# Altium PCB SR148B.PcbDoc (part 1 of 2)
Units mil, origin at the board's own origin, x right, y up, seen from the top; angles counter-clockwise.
Board outline 3900 x 2475 mil, 6 copper layers (Top Layer, Signal Layer 1, Signal Layer 2, Signal Layer 3, Signal Layer 4, Bottom Layer), stack 60.536 mil thick; 89 components, 26 nets, 178 pads, 295 vias.
Unrouted connection lines stored in the file: 1.
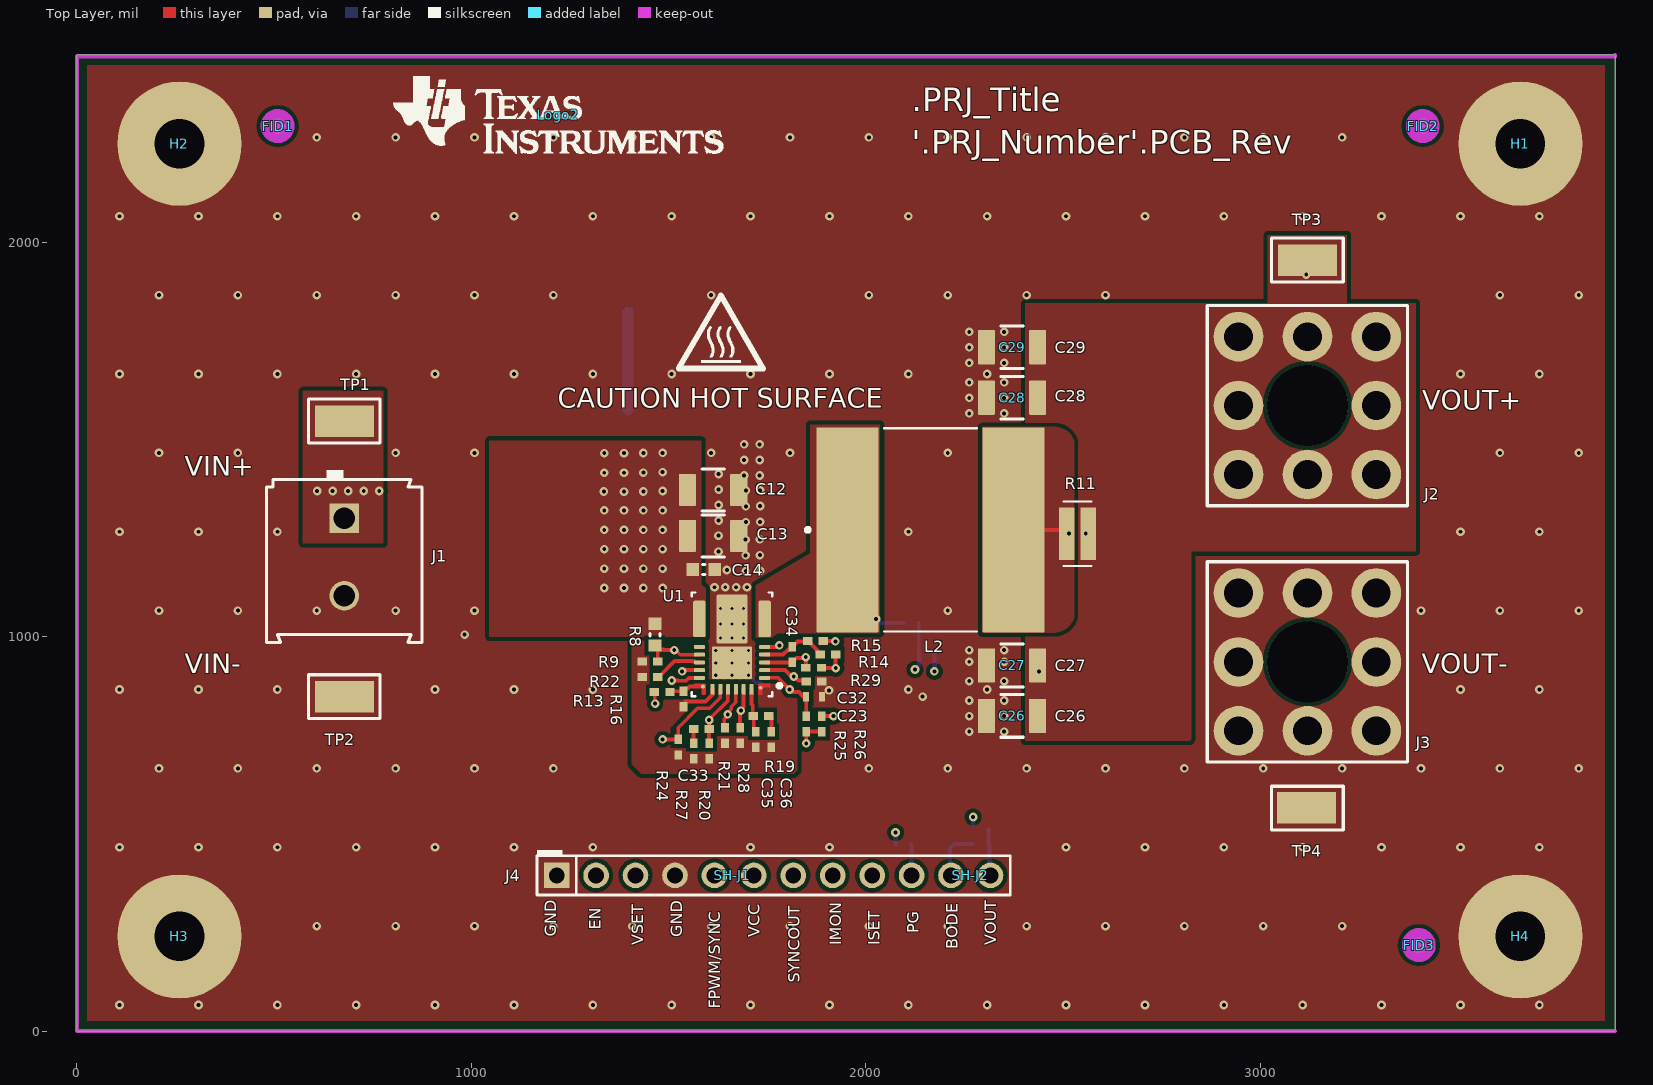
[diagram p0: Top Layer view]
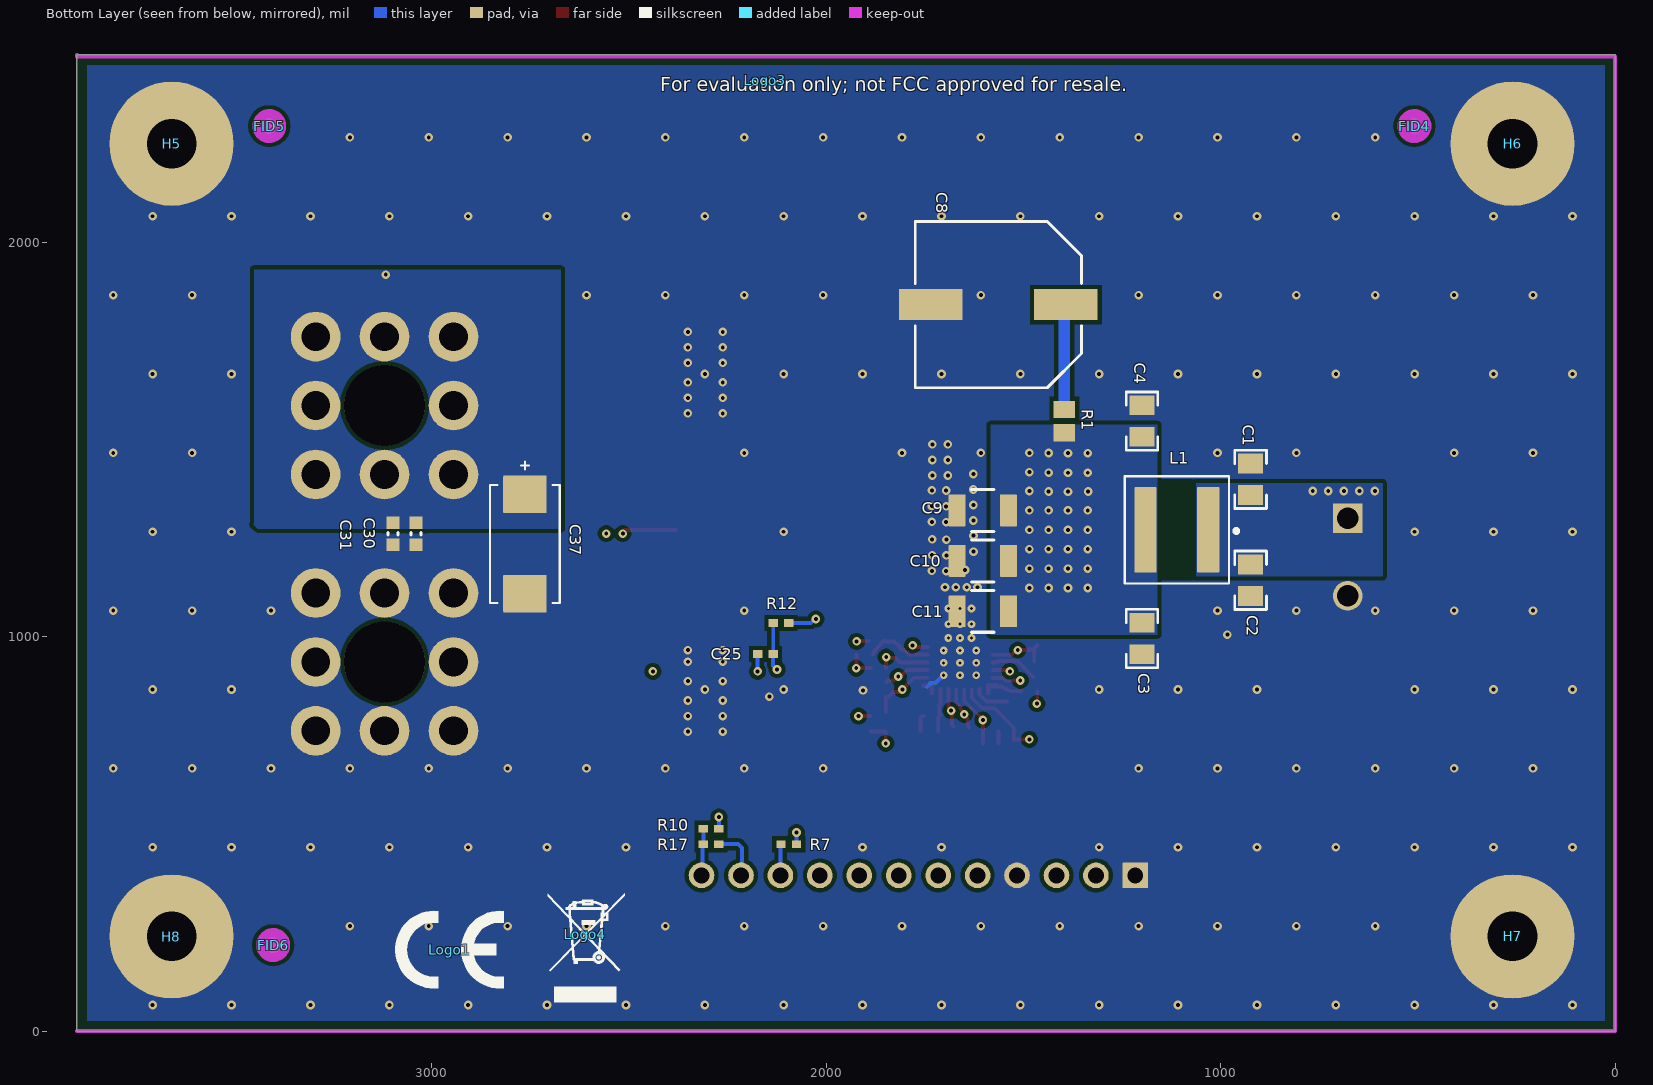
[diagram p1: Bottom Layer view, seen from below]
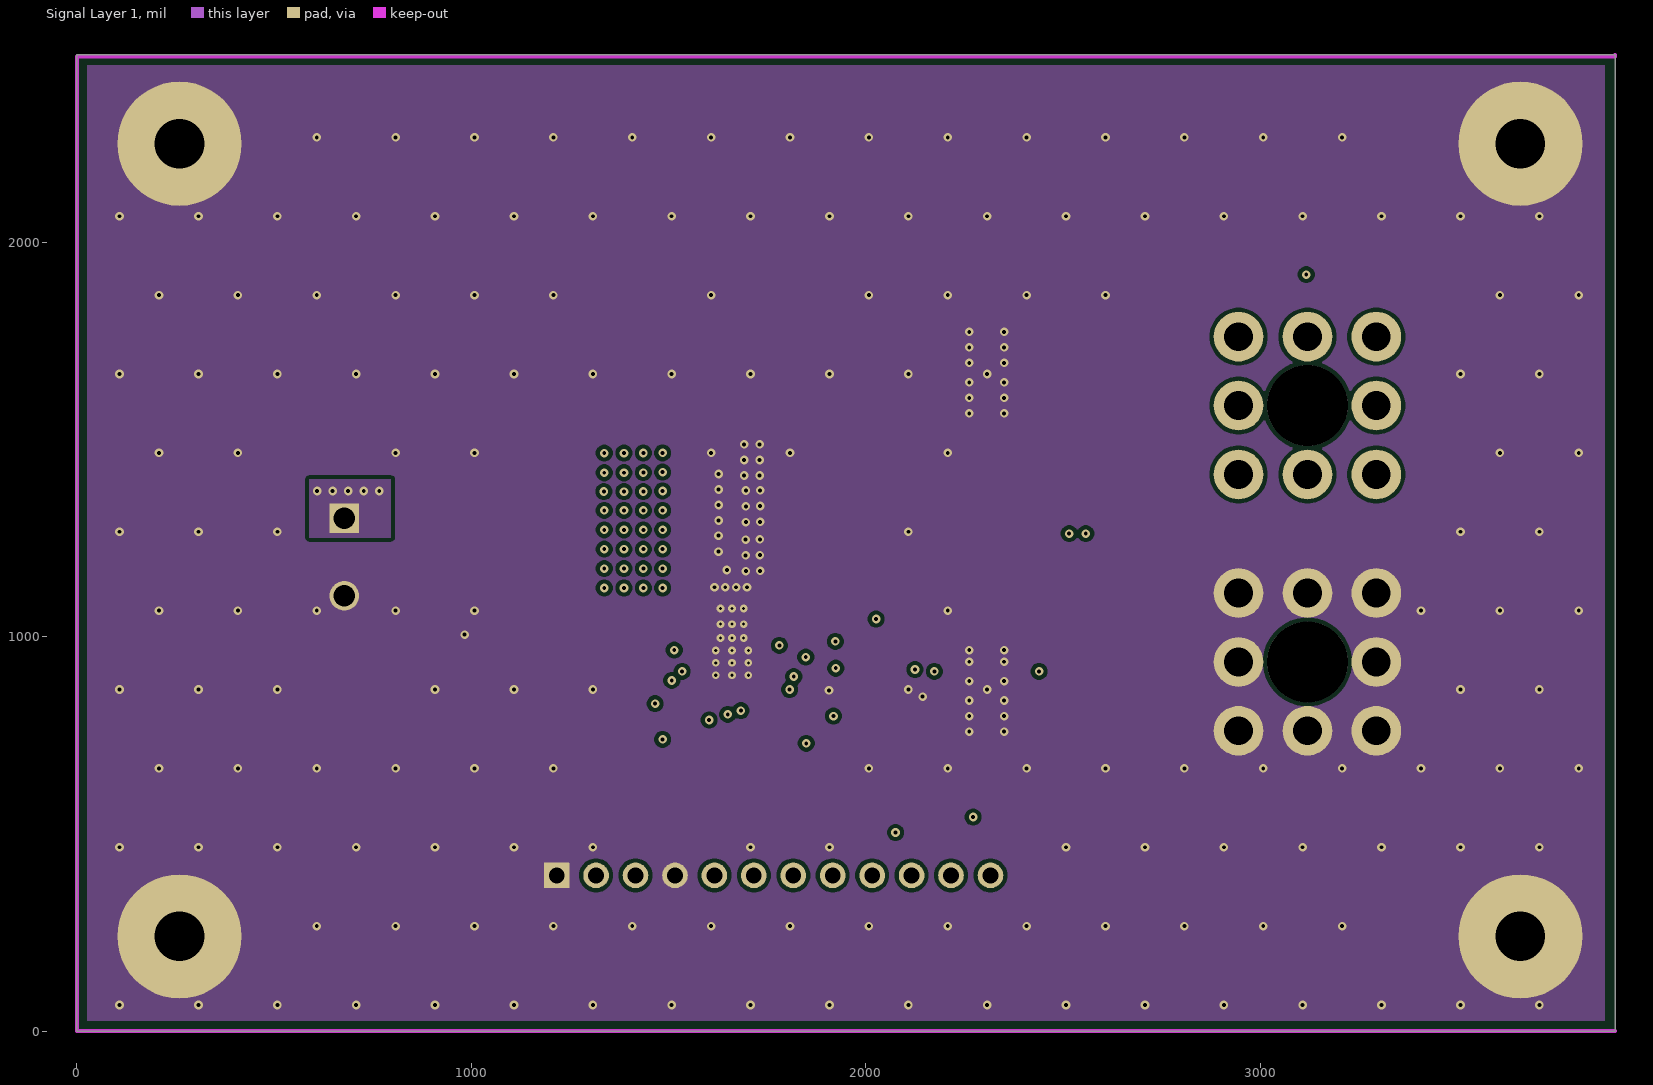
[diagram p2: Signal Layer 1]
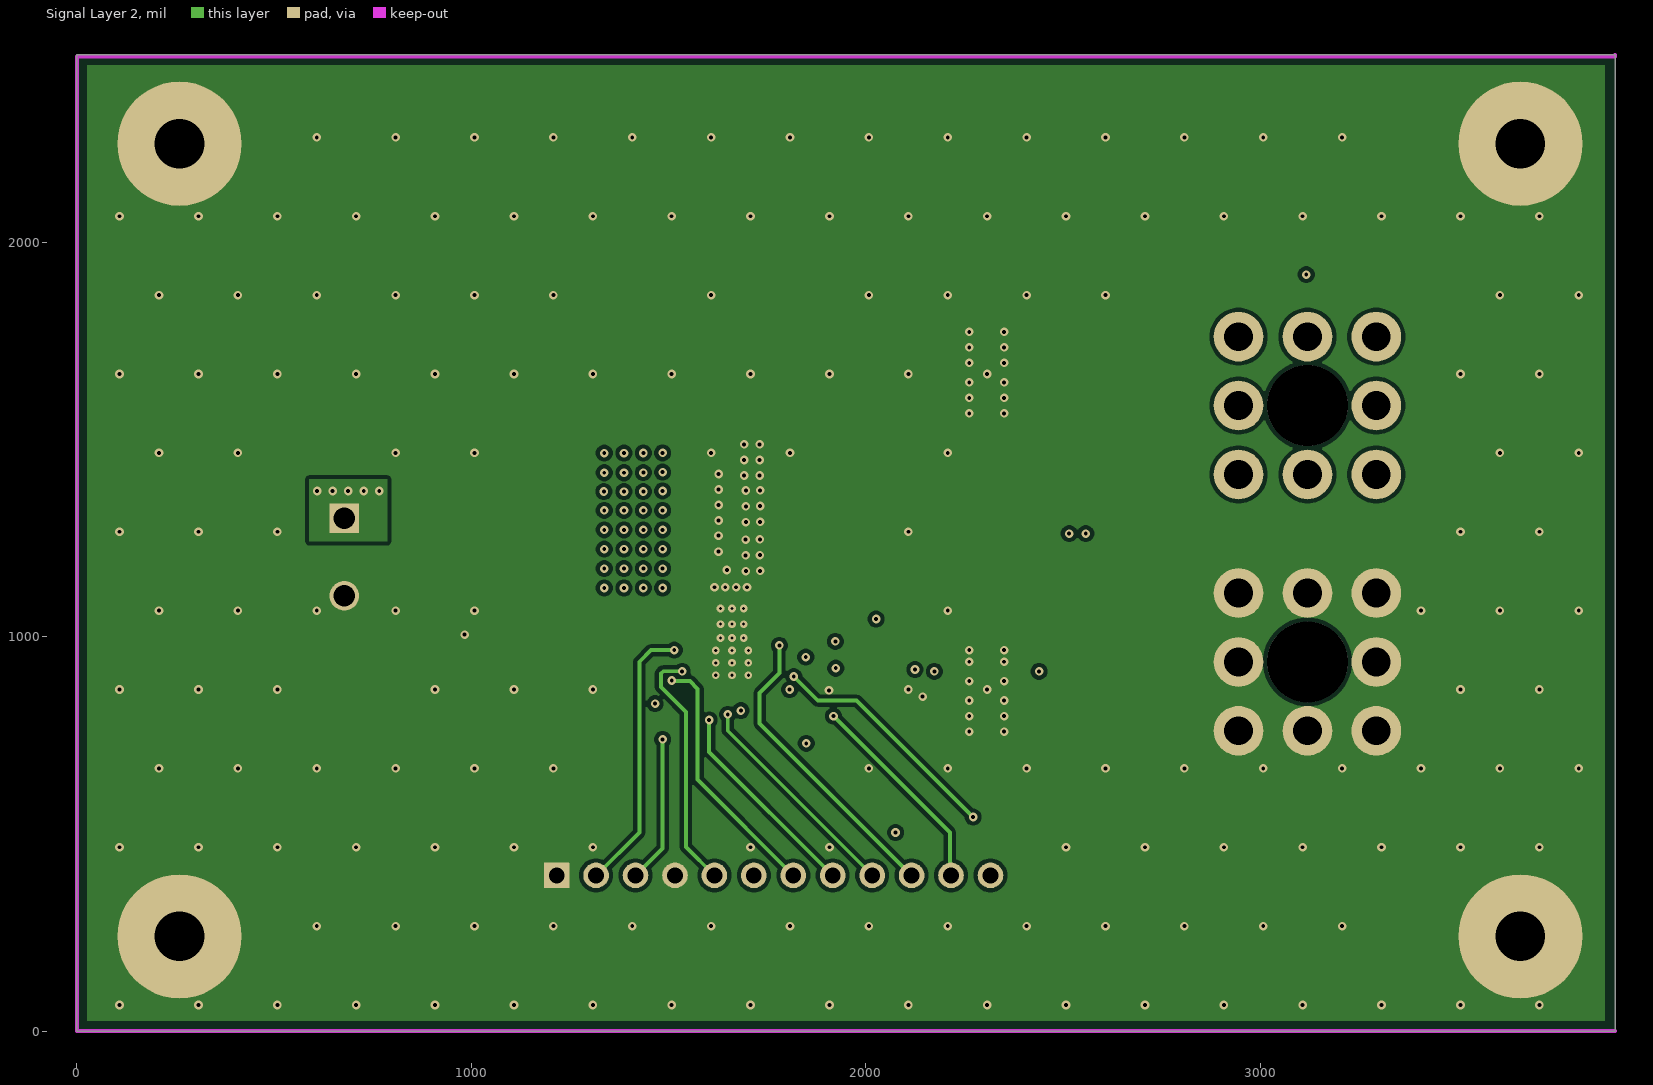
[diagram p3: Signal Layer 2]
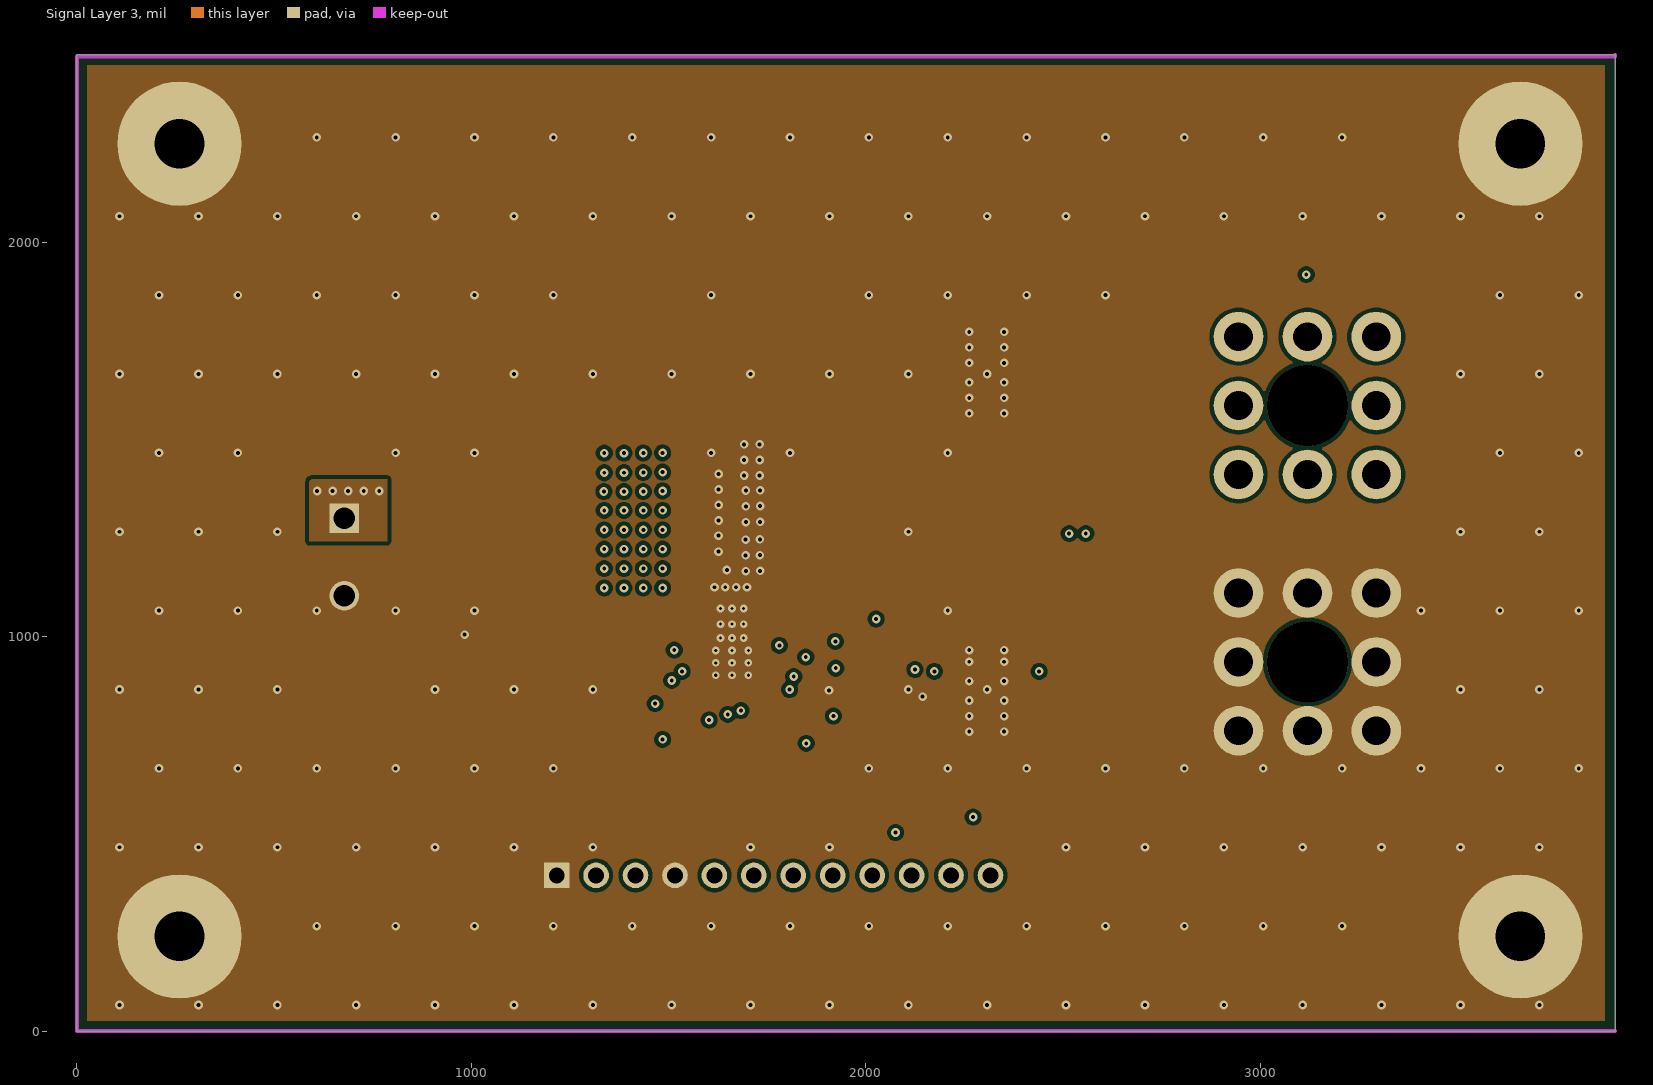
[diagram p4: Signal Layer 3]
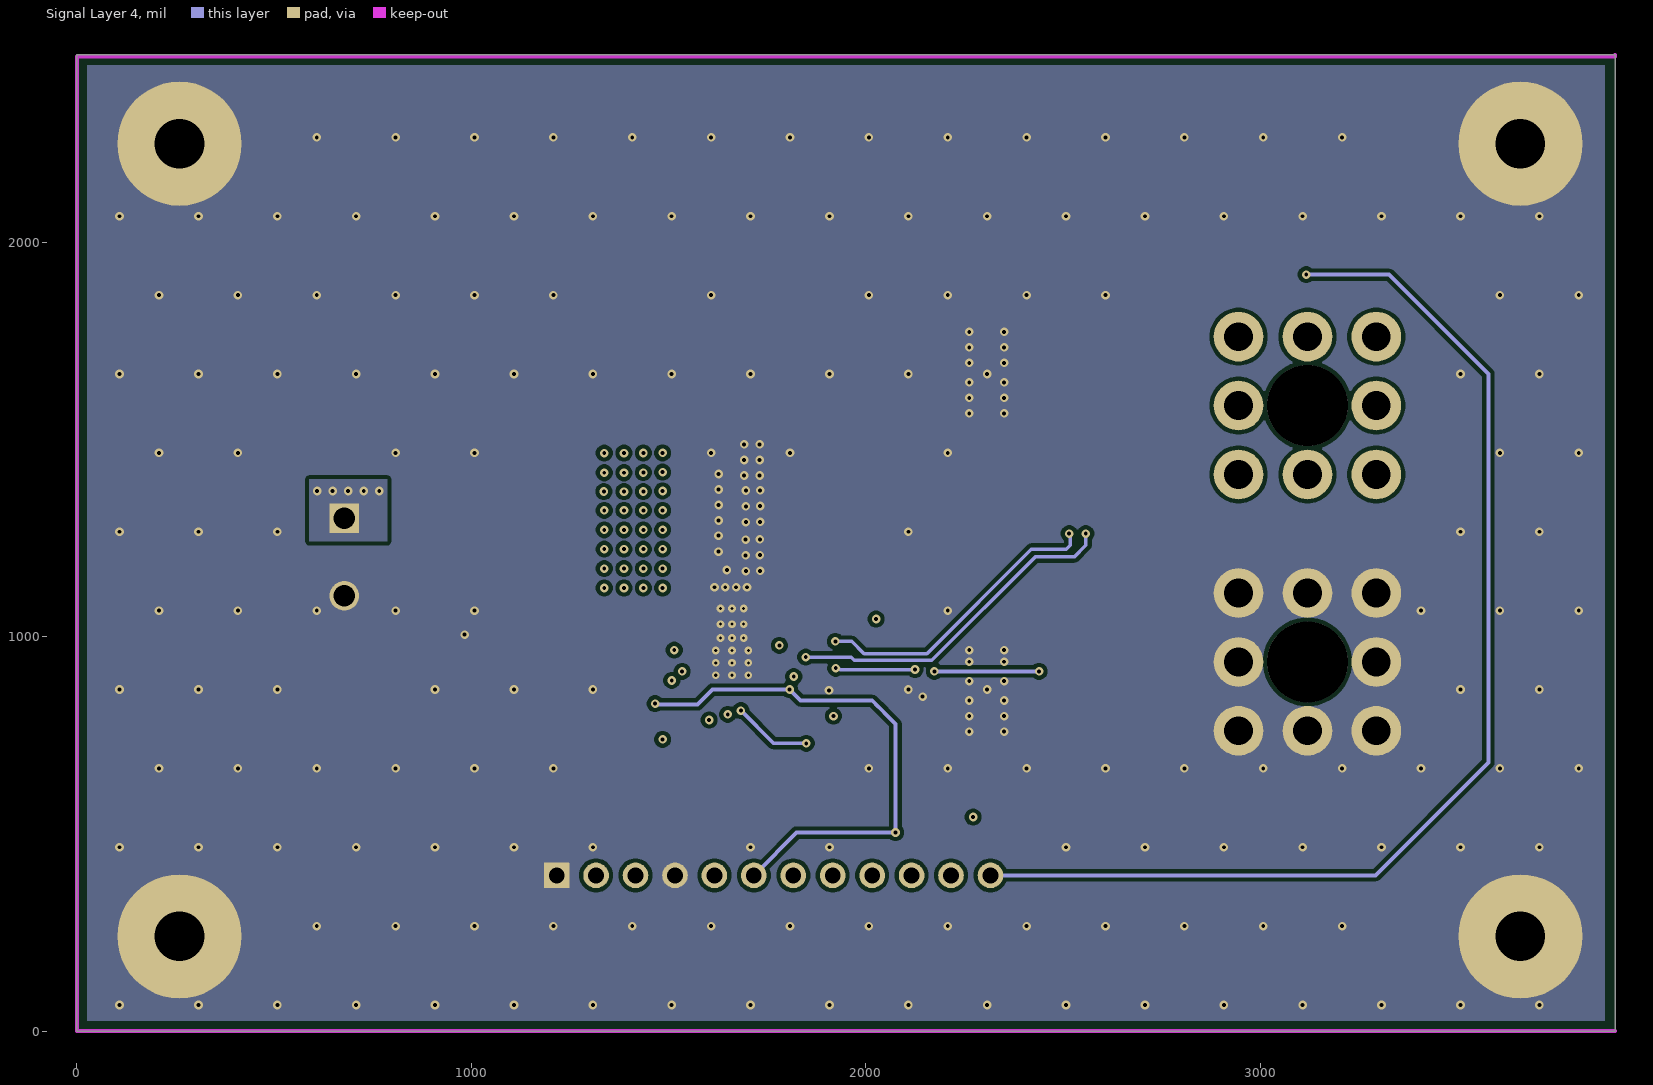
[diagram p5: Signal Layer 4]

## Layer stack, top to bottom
Top Solder: solder mask 0.4, Solder Resist, Dk 3.5
Top Layer: signal copper 2.756
Dielectric 1: prepreg 8, PP-006, Dk 4.1
Signal Layer 1: signal copper 2.756
Dielectric 2: prepreg 8, PP-006, Dk 4.1
Signal Layer 2: signal copper 2.756
Dielectric3: core 12, FR-4 High Tg, Dk 4.8
Signal Layer 3: signal copper 2.756
Dielectric 4: prepreg 8, PP-006, Dk 4.1
Signal Layer 4: signal copper 2.756
Dielectric 5: prepreg 8, PP-006, Dk 4.1
Bottom Layer: signal copper 2.756
Bottom Solder: solder mask 0.4, Solder Resist, Dk 3.5

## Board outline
0,0 3900,0 3900,2475 0,2475

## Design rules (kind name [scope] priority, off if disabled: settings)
AcuteAngle [All] p1: minimum=4.50000000000000E+0001 checktracksonly=FALSE
AssemblyTestPointUsage [All] p1: valid=2
BoardOutlineClearance BoardOutlineClearance_MountingHoles [OnCopper and InComponentClass('Mounting Holes')] p1: gap=39.37 ignorepadtopadclearanceinfootprint=FALSE
BoardOutlineClearance BoardOutlineClearance_Poly [OnCopper and IsPoly] p2: gap=25 ignorepadtopadclearanceinfootprint=FALSE
BoardOutlineClearance [OnCopper and Not InComponentClass('Logo') and not InComponentClass('FiducialMark') and not InRegion(1000,500,4000,800) and not InPoly] p3: gap=40 ignorepadtopadclearanceinfootprint=FALSE
Clearance [InNamedPolygon('TOP_LAYER_GND_P823') vs OnLayer('Top Layer')] p1: gap=10 ignorepadtopadclearanceinfootprint=FALSE
Clearance Clearance_FiducialMark [IsKeepOut and InComponentClass('FiducialMark') vs IsPad and InComponentClass('FiducialMark')] p2: gap=0 ignorepadtopadclearanceinfootprint=TRUE
Clearance Clearance_Keepouts [((IsTrack Or IsArc) And Not InPoly) And IsFree and IsKeepOut vs ((IsTrack Or IsArc) And Not InPoly) And IsFree and IsKeepOut] p3: gap=10 ignorepadtopadclearanceinfootprint=TRUE
Clearance Clearance_Poly [InPolygon] p4: gap=10 ignorepadtopadclearanceinfootprint=TRUE
Clearance Clearance_1 [All] p5: gap=7 ignorepadtopadclearanceinfootprint=TRUE except(0: SMDPad-Fill SMDPad-Poly SMDPad-Region)
ComponentClearance ComponentClearance_MountingHoles_FiducialMarks [InComponentClass('Mounting Holes') vs InComponentClass('FiducialMark')] p1: gap=50 collisioncheckmode=3 verticalgap=10 showdistances=FALSE
ComponentClearance ComponentClearance_Shunt [InComponentClass('Header') vs InComponentClass('Shunt')] p2: gap=0 collisioncheckmode=3 verticalgap=0 showdistances=FALSE
ComponentClearance ComponentClearance_Logo [InComponentClass('Logo')] p3: gap=30 collisioncheckmode=3 verticalgap=10 showdistances=FALSE
ComponentClearance ComponentClearance_ScrewToNut [(HasFootprint('NY PMS 440 0025 PH')) vs (HasFootprint('Keystone_1902C'))] p4: gap=5 collisioncheckmode=3 verticalgap=10 showdistances=FALSE
ComponentClearance ComponentClearance_MountingHoles_Headers [HasFootprint('NY PMS 440 0025 PH') vs HasFootprint('Keystone_1902E')] p5: gap=0 collisioncheckmode=3 verticalgap=0 showdistances=FALSE
ComponentClearance ComponentClearance_MountingHoles [InComponentClass('Mounting Holes') vs InComponentClass('Mounting Holes')] p6: gap=100 collisioncheckmode=3 verticalgap=0 showdistances=FALSE
ComponentClearance ComponentClearance_SmallPassives [HasFootprint('0201*') or HasFootprint('0402*') or HasFootprint('0508') or HasFootprint('0603*') or HasFootprint('0612') or HasFootprint('0805*') or HasFootprint('0815*') or HasFootprint('0830*') or HasFootprint('1206*') or HasFootprint('1210*') or HasFootprint('1808*') or HasFootprint('1812*') or HasFootprint('1825*') or HasFootprint('2010*') or HasFootprint('2220*') or HasFootprint('2225*') or HasFootprint('2512*') or HasFootprint('2728*') or HasFootprint('3518*') vs HasFootprint('0201*') or HasFootprint('0402*') or HasFootprint('0508') or HasFootprint('0603*') or HasFootprint('0612') or HasFootprint('0805*') or HasFootprint('0815*') or HasFootprint('0830*') or HasFootprint('1206*') or HasFootprint('1210*') or HasFootprint('1808*') or HasFootprint('1812*') or HasFootprint('1825*') or HasFootprint('2010*') or HasFootprint('2220*') or HasFootprint('2225*') or HasFootprint('2512*') or HasFootprint('2728*') or HasFootprint('3518*')] p7: gap=10 collisioncheckmode=3 verticalgap=10 showdistances=FALSE
ComponentClearance ComponentClearance_THtoSMT [IsThruComponent vs IsSMTComponent] p8: gap=0 collisioncheckmode=3 verticalgap=0 showdistances=FALSE
ComponentClearance ComponentClearanceConnectors [HasFootprint('FP-CB70-14-190_CONN_TERM_RECT_LUG-MFG') vs HasFootprint('Keystone_6096')] p9: gap=0 collisioncheckmode=3 verticalgap=0 showdistances=FALSE
ComponentClearance ComponentClearance_Inductors [HasFootprint('SER2915L') vs HasFootprint('IHLP-6767GZ')] p10: gap=0 collisioncheckmode=3 verticalgap=0 showdistances=FALSE
ComponentClearance ComponentClearance_indInput [HasFootprint('HC2LP') vs HasFootprint('XAL8080')] p11: gap=0 collisioncheckmode=3 verticalgap=0 showdistances=FALSE
ComponentClearance ComponentClearance_THtoTH [IsThruComponent vs IsThruComponent] p12: gap=20 collisioncheckmode=3 verticalgap=30 showdistances=FALSE
ComponentClearance [All] p13: gap=0 collisioncheckmode=3 verticalgap=0 showdistances=TRUE
DiffPairsRouting [All] p1: maxlimit=100 minlimit=10 mostfreqgap=10 toplayer_minwidth=15 toplayer_maxwidth=15 toplayer_prefwidth=15 midlayer1_minwidth=15 midlayer1_maxwidth=15 midlayer1_prefwidth=15 midlayer2_minwidth=15 midlayer2_maxwidth=15 midlayer2_prefwidth=15 midlayer3_minwidth=15 midlayer3_maxwidth=15 midlayer3_prefwidth=15 midlayer4_minwidth=15 midlayer4_maxwidth=15 midlayer4_prefwidth=15 bottomlayer_minwidth=15 bottomlayer_maxwidth=15 bottomlayer_prefwidth=15 maxuncoupledlength=1000
FabricationTestPointUsage TestPointUsage [All] p1: valid=2 allowmultiple=FALSE
FabricationTestpoint Testpoint [All] p1: side=3 testpointundercomponent=TRUE minsize=40 maxsize=100 preferedsize=60 minholesize=0 maxholesize=40 preferedholesize=32 testpointgrid=1 allowsidetop=TRUE allowsidebottom=TRUE usegrid=TRUE gridtolerance=0.01
FanoutControl Fanout_LCC [IsLCC] p1: bgadir=Out bgaviamode=Centered fanoutstyle=Auto fanoutdirection=Alternating viagrid=1 // Fanout_LCC (Default Rule)
FanoutControl Fanout_BGA [IsBGA] p2: bgadir=Out bgaviamode=Centered fanoutstyle=Auto fanoutdirection=Alternating viagrid=1 // Fanout_BGA (Default Rule)
Height [All] p1: minheight=0 maxheight=1500 prefheight=500
HoleSize [All] p1: absolutevalues=TRUE maxlimit=300 minlimit=7.87 maxpercent=80.000 minpercent=20.000
MinimumAnnularRing MinimumAnnularRing_ThermalPadVias [IsVia and InAnyComponent] p1: minimumring=5.91
MinimumAnnularRing [All] p2: minimumring=0
MinimumSolderMaskSliver MinimumSolderMaskSliver_Logo [InComponentClass('Logo') vs InComponentClass('Logo')] p1: minsoldermaskwidth=0.7
MinimumSolderMaskSliver [All] p2: minsoldermaskwidth=3.94
PlaneClearance [All] p1: clearance=10
PlaneConnect [All] p1: planeconnectstyle=Direct reliefexpansion=10 reliefentries=4 reliefconductorwidth=10 reliefairgap=10
PolygonConnect PolygonConnectStyle_1 [HasFootprint('TSW-112-07-G-S')] p1: connectstyle=Direct reliefconductorwidth=10 reliefentries=4 polygonreliefangle="90 Angle" airgapwidth=10
PolygonConnect [All] p2: connectstyle=Direct reliefconductorwidth=10 reliefentries=4 polygonreliefangle="90 Angle" airgapwidth=10
RoutingVias ThermalPadVias [IsVia and InAnyComponent] p1: holewidth=7.87 width=19.68 viastyle="Through Hole" minholewidth=7.87 minwidth=19.68 maxholewidth=16 maxwidth=32
RoutingVias [All] p2: holewidth=10 width=22 viastyle="Through Hole" minholewidth=7.87 minwidth=20 maxholewidth=40 maxwidth=65
ShortCircuit [InNet('VOUT') vs InNet('VOUT')] p1: allowed=TRUE
SilkToSilkClearance SilkToSilkClearance_Pb-FreeLogo [(HasFootprint('Pb-Free_Overlay_Medium') OR HasFootprint('Pb-Free_Overlay_Small')) vs (HasFootprint('Pb-Free_Overlay_Medium') OR HasFootprint('Pb-Free_Overlay_Small'))] p1: silktosilkclearance=0
SilkToSilkClearance [All] p2: silktosilkclearance=3.94
SilkToSolderMaskClearance SilkToComponentPadClearance [(IsPad or IsFill or IsRegion) and InAnycomponent] p1: minsilkscreentomaskgap=5 clearancetoexposedcopper=TRUE
SilkToSolderMaskClearance "Silk to Solder Mask Opening" [All] p2: minsilkscreentomaskgap=3.94 clearancetoexposedcopper=FALSE
SolderMaskExpansion [All] p1: expansion=1.97 istentingtop=FALSE
SupplyNets "Schematic Supply Nets_4" [InNet('VIN')] p1: voltage=0.000
SupplyNets "Schematic Supply Nets_3" [InNet('VCC')] p2: voltage=0.000
SupplyNets "Schematic Supply Nets_2" [InNet('VOUT')] p3: voltage=0.000
SupplyNets "Schematic Supply Nets_1" [InNet('AGND')] p4: voltage=0.000
SupplyNets "Schematic Supply Nets" [InNet('GND')] p5: voltage=0.000
UnRoutedNet [InNet('PGND')] p1: checkbadconnections=TRUE
Width [All] p1: maxlimit=100 minlimit=6 preferedwidth=10 checkconnectedcopper=TRUE
14 further rules are at their usual default settings.

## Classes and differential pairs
component class FiducialMark: FID1 FID2 FID3 FID4 FID5 FID6
component class "Mounting Holes": H1 H2 H3 H4
component class Logo: Logo2
component class SR148B_Hardware: !PCB1 "CAUTION HOT SURFACE" FID1 FID2 FID3 FID4 FID5 FID6 H1 H2 H3 H4 H5 H6 H7 H8 Logo1 Logo2 Logo3 Logo4 SH-J1 SH-J2 ZZ1 ZZ2 ZZ3 ZZ4 ZZ5 ZZ6
component class AssemblyNote: ZZ1 ZZ2 ZZ3 ZZ4 ZZ5 ZZ6
component class SR148B: C1 C2 C3 C4 C8 C9 C10 C11 C12 C13 C14 C23 C25 C26 C27 C28 C29 C30 C31 C32 C33 C34 C35 C36 C37 J1 J2 J3 J4 L1 L2 R1 R7 R8 R9 R10 R11 R12 R13 R14 R15 R16 R17 R19 R20 R21 R22 R24 R25 R26 R27 R28 R29 TP1 TP2 TP3 TP4 U1 U2_S1
component class Header: J4

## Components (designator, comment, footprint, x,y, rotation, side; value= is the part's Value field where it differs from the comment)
C1 "GRM21BR72A474KA73L" 0805_HV 924,1398.95 r90 bottom value=0.47uF
C2 "GRM21BR72A474KA73L" 0805_HV 924,1143.05 r270 bottom value=0.47uF
C3 "GRM21BR72A474KA73L" 0805_HV 1199.59,995.41 r270 bottom value=0.47uF
C4 "GRM21BR72A474KA73L" 0805_HV 1199.59,1546.59 r90 bottom value=0.47uF
C8 "EEE-FK2A330P" SM_RADIAL_G 1563.76,1841.87 r0 bottom value=33uF
C9 "GRM32EC72A106KE05L" FP-GRM32EC72A106KE05L_1210-MFG 1603.13,1320.21 r0 bottom
C10 "GRM32EC72A106KE05L" FP-GRM32EC72A106KE05L_1210-MFG 1603.13,1192.26 r0 bottom
C11 "GRM32EC72A106KE05L" FP-GRM32EC72A106KE05L_1210-MFG 1603.13,1064.31 r0 bottom
C12 "GRM32EC72A106KE05L" FP-GRM32EC72A106KE05L_1210-MFG 1613,1372 r0 top
C13 "GRM32EC72A106KE05L" FP-GRM32EC72A106KE05L_1210-MFG 1613,1255.53 r0 top
C14 "CGA3E2X8R2A103K080AD" 0603L 1589.29,1169.94 r0 top value=0.01uF
C23 "GRT155C71A225KE13" 0402_070 1868.88,847.77 r0 top value=2.2uF
C25 "CGA2B3X7R1E104K050BB" 0402L 2154,956.04 r0 bottom value=0.1uF
C26 "GCM32EC71A476KE02K" FP-GCM32EC71A476KE02K_1210-MFG 2371,799 r0 top
C26 "CGA6P3X7R1E226M250AB" FP-CGA6P3X7R1E226M250AB_1210-MFG 2371,799 r0 top value=22µF
C27 "GCM32EC71A476KE02K" FP-GCM32EC71A476KE02K_1210-MFG 2371,927 r0 top
C27 "CGA6P3X7R1E226M250AB" FP-CGA6P3X7R1E226M250AB_1210-MFG 2371,927 r0 top value=22µF
C28 "CGA6P3X7R1E226M250AB" FP-CGA6P3X7R1E226M250AB_1210-MFG 2371,1606 r0 top value=22µF
C28 "GCM32EC71A476KE02K" FP-GCM32EC71A476KE02K_1210-MFG 2371,1606 r0 top
C29 "CGA6P3X7R1E226M250AB" FP-CGA6P3X7R1E226M250AB_1210-MFG 2371,1734 r0 top value=22µF
C29 "GCM32EC71A476KE02K" FP-GCM32EC71A476KE02K_1210-MFG 2371,1734 r0 top
C30 "C0603C104K5RACTU" 0603L 3040,1261 r270 bottom value=0.1uF
C31 "C0603C104K5RACTU" 0603L 3099,1261 r270 bottom value=0.1uF
C32 "CGA2B3X7R1E104K050BB" 0402L 1869,886 r0 top value=0.1uF
C33 "CGA2B3X8R1H103K050BB" 0402L 1583.45,766 r0 top value=0.01uF
C34 "CGA2B2C0G1H101J050BA" 0402L 1814,955 r270 top value=100pF
C35 "CGA2B2C0G1H470J050BA" 0402L 1721,739.5 r270 top value=47pF
C36 "GRM155R71H272KA01D" 0402L 1760.61,739.5 r270 top value=2700pF
C37 "ECASD61C107M012KA0" FP-ECASD61C107M012KA0_2917-MFG 2764,1235 r90 bottom value=100µF
"CAUTION HOT SURFACE" "CAUTION HOT SURFACE" IEC_HotSurface_Small 1632.66,1772.97 r0 top
FID1 "Fiducial" Fiducial10-20 508.78,2294.74 r90 top
FID2 "Fiducial" Fiducial10-20 3412.32,2294.74 r90 top
FID3 "Fiducial" Fiducial10-20 3402.48,217.97 r90 top
FID4 "Fiducial" Fiducial10-20 508.78,2294.74 r90 bottom
FID5 "Fiducial" Fiducial10-20 3412.32,2294.74 r90 bottom
FID6 "Fiducial" Fiducial10-20 3402.48,217.97 r90 bottom
H1 "NY PMS 440 0025 PH" "NY PMS 440 0025 PH" 3660,2250 r0 top
H2 "NY PMS 440 0025 PH" "NY PMS 440 0025 PH" 260,2250 r0 top
H3 "NY PMS 440 0025 PH" "NY PMS 440 0025 PH" 260,240 r0 top
H4 "NY PMS 440 0025 PH" "NY PMS 440 0025 PH" 3660,240 r0 top
H5 "1902C" Keystone_1902E 3660,2250 r180 bottom
H6 "1902C" Keystone_1902E 260,2250 r180 bottom
H7 "1902C" Keystone_1902E 260,240 r180 bottom
H8 "1902C" Keystone_1902E 3660.63,239.37 r180 bottom
J1 "282856-2" TE_282856-2 677.94,1202.1 r270 top
J2 "74655095R" FP-74655095R_CONN_TERM_10MM0_10MM0-MFG 3120,1586 r0 top
J3 "74655095R" FP-74655095R_CONN_TERM_10MM0_10MM0-MFG 3120,936 r0 top
J4 "TSW-112-07-G-S" TSW-112-07-G-S 1766.3,394.69 r0 top
L1 "XGL6060-332MEC" FP-XGL6060-332MEC_SMT_6MM51_6MM71-MFG 1111.01,1271 r0 bottom value=3.3uH
L2 "VCUD128T-4R7MS8" FP-VCUD128T-4R7MS8_SMT_IND_13MM3_12MM8-MFG 2164.16,1271 r0 top value=4.7uH
Logo1 "CE Mark" CE_Mark_5mm 2954.99,206.33 r180 bottom
Logo2 "Texas Instruments" TI_Stacked_Overlay_Small 1220.47,2322.83 r0 top
Logo3 "FCC disclaimer" FCC_disclaimer 2155,2411 r180 bottom
Logo4 "WEEE logo" WEEE_Minimum 2610.87,244.86 r180 bottom
R1 "ERJ-6GEY0R00V" 0805L 1396.44,1546.59 r270 bottom value=0
R7 "AC0402FR-07100KL" 0402L 2095.26,473.76 r180 bottom value=100k
R8 "RC0603FR-07200KL" 0603L 1465.34,1005.25 r90 top value=200k
R9 "ERJPA2F1002X" 0402L 1453,937.2 r0 top value=10.0k
R10 "CRCW04021R00FKED" 0402L 2292.11,513.13 r0 bottom value=1.00
R11 "KRL3216E-C-R001-J-T5" FP-KRL3216E-C-R001-J-T5_0612-MFG 2537,1261 r0 top value=1m
R12 "ERJPA2F1002X" 0402L 2114.94,1034.78 r0 bottom value=10.0k
R13 "CRCW040254K9FKED" 0402L 1483.82,860 r180 top value=54.9k
R14 "RK73Z1ETTP" 0402L 1904,955 r0 top value=0
R15 "ERJ-2RKF49R9X" 0402L 1873,989 r0 top value=49.9
R16 "CRCW040254K9FKED" 0402L 1538.27,842.1 r90 top value=54.9k
R17 "ERJ-2RKF49R9X" 0402L 2292.11,473.76 r0 bottom value=49.9
R19 "CRCW040211K0FKED" 0402L 1734.29,798.59 r180 top value=11.0k
R20 "CRCW04028K66FKED" 0402L 1603.13,709.98 r90 top value=8.66k
R21 "CRCW040290K9FKED" 0402L 1643,749.35 r90 top value=90.9k
R22 "CRCW040223K7FKED" 0402L 1453,897.63 r0 top value=23.7k
R24 "CRCW040290K9FKED" 0402L 1524.39,719.82 r90 top value=90.9k
R25 "RK73Z1ETTP" 0402L 1849.2,778.87 r90 top value=0
R26 "CRCW040254K9FKED" 0402L 1888.57,778.87 r90 top value=54.9k
R27 "RK73Z1ETTP" 0402L 1563.76,709.98 r90 top value=0
R28 "ERA-2AEB4991X" 0402L 1681.87,749.35 r90 top value=4.99k
R29 "AC0402FR-07100KL" 0402L 1868,921 r0 top value=100k
SH-J1 "M7582-05" Harwin_M7582-05 1662,395 r180 top
SH-J2 "M7582-05" Harwin_M7582-05 2265,395 r180 top
TP1 "5019" Keystone_5019#1 677.94,1546.59 r0 top
TP2 "5019" Keystone_5019#1 677.94,847.77 r0 top
TP3 "5019" Keystone_5019#1 3120,1955 r0 top
TP4 "5019" Keystone_5019#2 3120,565 r0 top
U1 "LMG708B0VBTR" VBT0022B-MFG 1661,979 r180 top
ZZ1 "This Assembly Note is for PCB labels only" AssemblyNoteLabel 19.68,3357.28 r0 top
ZZ2 "These assemblies are ESD sensitive, ESD precautions shall be observed." AssemblyNote 19.68,3257.28 r0 top
ZZ3 "These assemblies must be clean and free from flux and all contaminants. Use of no clean flux is not acceptable." AssemblyNote 19.68,3157.28 r0 top
ZZ4 "These assemblies must comply with workmanship standards IPC-A-610 Class 2, unless otherwise specified." AssemblyNote 19.68,3061.02 r0 top
ZZ5 "Install Shunt Jumper SH-J1 onto J4 Pins 5-6" AssemblyNote 19.68,2952.76 r0 top
ZZ6 "Install Shunt Jumper SH-J2 onto J4 Pins 11-12" AssemblyNote 22,2844 r0 top

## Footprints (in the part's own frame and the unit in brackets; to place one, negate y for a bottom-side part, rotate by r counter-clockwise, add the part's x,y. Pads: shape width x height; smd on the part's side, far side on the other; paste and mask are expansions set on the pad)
0402_070 [mil] "SMD, 2-Leads, Body 1.2x0.7mm, Height 0.7mm"
  rect 15x24 smd: 1(-20,0) 2(20,0)
  body extent -24,-14 24,14, height 28
0402L [mm] "0402 from SM-752 data"
  rect 0.6x0.5 smd: 1(-0.5,0) 2(0.5,0)
  body extent -0.55,-0.3 0.55,0.3, height 0.6
0603L [mm] "0603 from SM-752 data"
  rect 0.8x0.85 smd: 1(-0.7,0) 2(0.7,0)
  silkscreen extent -0.07,-0.33 0.07,0.33, body extent -0.87,-0.47 0.87,0.47, height 1
0805_HV [mil] "0805 with 30mil clearance between pads"
  rect 50x63 smd: 1(-40,0) 2(40,0)
  silkscreen extent -74,-40 74,40, body extent -43,-29 43,29, height 57
0805L [mm] "0805 from SM-752 data"
  rect 1.1x1.4 smd: 1(-0.75,0) 2(0.75,0)
  body extent -1.1,-0.72 1.1,0.72, height 1.45
AssemblyNote [mil] "Assembly Note"
AssemblyNoteLabel [mil] "Assembly Note for PCB Labels"
CE_Mark_5mm [mil] "Minimum text height for CE Mark"
  silkscreen extent -138,-98 138,98
FCC_disclaimer [mil]
Fiducial10-20 [mm]
  round 1 smd mask+0.5: 1(0,0)
  Top Layer keep-out circle w1.178: c0,0 r0.5
FP-74655095R_CONN_TERM_10MM0_10MM0-MFG [mm]
  round 3.2 hole 1.85 paste-2539.97 mask+0: 1(-4.435,-4.435) 1(-4.435,0) 1(-4.435,4.435) 1(0,-4.435) 1(0,4.435) 1(4.435,-4.435) 1(4.435,0) 1(4.435,4.435)
  round 5.2 hole 5.2 unplated paste-2539.97 mask+0: ""(0,0)
  silkscreen extent -6.45,-6.45 6.45,6.45, body extent -6.13,-6.13 6.13,6.13, height 0.25
FP-CGA6P3X7R1E226M250AB_1210-MFG [mm]
  rrect9% 1.1x2.2 smd paste+0 mask+0: 1(-1.65,0) 2(1.65,0)
  silkscreen extent -0.72,-1.4 0.72,1.4, body extent -2.3,-1.5 2.3,1.5, height 0.25
FP-ECASD61C107M012KA0_2917-MFG [mm] "Recommended Land Pattern"
  rrect4% 2.4x2.8 smd paste+0 mask+0: 1(-3.2,0) 2(3.2,0)
  silkscreen extent -3.8,-2.25 5.3,2.25, body extent -3.65,-2.15 3.65,2.15, height 3.1
FP-GCM32EC71A476KE02K_1210-MFG [mm]
  rrect9% 1.1x2.05 smd paste+0 mask+0: 1(-1.65,0) 2(1.65,0)
  silkscreen extent -0.72,-1.35 0.72,1.35, body extent -2.3,-1.45 2.3,1.45, height 0.25
FP-GRM32EC72A106KE05L_1210-MFG [mm]
  rrect9% 1.1x2.05 smd paste+0 mask+0: 1(-1.65,0) 2(1.65,0)
  silkscreen extent -0.72,-1.35 0.72,1.35, body extent -1.6,-1.25 1.6,1.25, height 2.7
FP-KRL3216E-C-R001-J-T5_0612-MFG [mm] "Recommended Land Pattern"
  rrect10% 1x3.4 smd paste+0 mask+0: 1(-0.7,0) 2(0.7,0)
  silkscreen extent -0.9,-2.07 0.9,2.07, body extent -1.3,-1.8 1.3,1.8, height 0.25
FP-VCUD128T-4R7MS8_SMT_IND_13MM3_12MM8-MFG [mm] "Recommended Land Pattern"
  rrect3% 4x13.2 smd paste+0 mask+0: 1(-5.35,0) 2(5.35,0)
  silkscreen extent -8.02,-6.55 2.98,6.55, body extent -7.45,-6.7 7.45,6.7, height 0.25
FP-XGL6060-332MEC_SMT_6MM51_6MM71-MFG [mm]
  rrect7% 1.43x5.5 smd paste+0 mask+0: 1(-2.02,0) 2(2.02,0)
  silkscreen extent -3.95,-3.45 3.35,3.45, body extent -3.25,-3.35 3.25,3.35, height 6.1
Harwin_M7582-05 [mil] "Single Operation 2.54mm Pitch Open Top Jumper Socket"
  body extent -98,-47 98,47, height 236
IEC_HotSurface_Small [mil]
  silkscreen extent -107,-93 107,92
Keystone_1902E [mil] "Hex Standoff, 4-40 threaded, nylon"
  round 1 on Mech4: 0(0,0)
  body extent -145,-126 146,126, height 1001
Keystone_5019#1 [mm] "Test Point, Miniature, SMT"
  rect 3.8x2.03 smd: 1(0,0)
  silkscreen extent -2.31,-1.42 2.31,1.42, body extent -1.9,-1.02 1.9,1.02, height 2.29
Keystone_5019#2 [mm] "Test Point, Miniature, SMT"
  rect 3.8x2.03 smd: 1(-0.05,0.015)
  silkscreen extent -2.31,-1.42 2.31,1.42, body extent -1.9,-1.02 1.9,1.02, height 2.29
"NY PMS 440 0025 PH" [mm] "4-40 nylon screw and mounting hole"
  round 8 hole 3.2: 1(0,0)
  body extent -3.3,-3.3 3.3,3.3, height 2.69
SM_RADIAL_G [mm] "10 x 10.2mm:  Panasonic G"
  rect 4.1x2 smd: 1(-4.35,0) 2(4.35,0)
  silkscreen extent -5.35,-5.35 5.35,5.35, body extent -5.25,-5.25 5.25,5.25, height 10.5
TE_282856-2 [mm] "TH, 2-Leads, Body 10x10mm, Pitch 5mm"
  rect 1.9x1.9 hole 1.4: 1(-2.5,0)
  round 1.9 hole 1.4: 2(2.5,0)
  silkscreen extent -5.61,-5 5.5,5, body extent -5,-5 5.5,5, height 19
TI_Stacked_Overlay_Small [mil]
  silkscreen extent -418,-98 418,98
TSW-112-07-G-S [mm] "Samtec 100mil, 1x12, 230 mil above insulator"
  rrect6% 1.65x1.65 hole 1.016 mask+0: 1(-13.97,0)
  round 1.65 hole 1.016 mask+0: 2(-11.43,0) 3(-8.89,0) 4(-6.35,0) 5(-3.81,0) 6(-1.27,0) 7(1.27,0) 8(3.81,0) 9(6.35,0) 10(8.89,0) 11(11.43,0) 12(13.97,0)
  silkscreen extent -15.24,-1.27 15.24,1.65, body extent -15.24,-1.27 15.24,1.27, height 8.38
VBT0022B-MFG [mm] "Recommended Land Pattern"
  round 0.234 smd paste+0 mask+0: 1(-1.837,2.762)
  rrect40% 0.7x0.25 smd paste+0 mask+0: 2(-2.1,2.125) 3(-2.1,1.625) 4(-2.1,1.125) 5(-2.1,0.625) 6(-2.1,0.125) 10(2.1,0.125) 11(2.1,0.625) 12(2.1,1.125) 13(2.1,1.625) 14(2.1,2.125)
  rrect25% 0.8x2.35 smd paste-1000 mask-1000: 7(-2.1,-1.675) 9(2.1,-1.675)
  rrect10% 2x3.15 smd paste-1000 mask-1000: 8(0,-1.675)
  round 0.265 smd paste+0 mask+0: 15(1.875,2.675)
  rrect40% 0.25x0.7 smd paste+0 mask+0: 16(1.25,2.85) 17(0.75,2.85) 18(0.25,2.85) 19(-0.25,2.85) 20(-0.75,2.85) 21(-1.25,2.85)
  rrect10% 2.6x2.1 smd paste-1000 mask-1000: 22(0,1.15)
  Top Layer region: -2.4,2.5 -2.419,2.504 -2.435,2.515 -2.446,2.531 -2.45,2.55 -2.45,2.55 -2.45,2.7 -2.443,2.725 -2.425,2.743 -2.4,2.75 -2.4,2.75 -2.05,2.75 -2.012,2.758 -1.979,2.779 -1.958,2.812 -1.95,2.85 -1.95,2.85 -1.95,3.15 -1.943,3.175 -1.925,3.193 -1.9,3.2 -1.9,3.2 -1.75,3.2 -1.725,3.193 -1.707,3.175 -1.7,3.15 -1.7,3.15 -1.7,2.55 -1.704,2.531 -1.715,2.515 -1.731,2.504 -1.75,2.5 -1.75,2.5
  Top Layer region: 2.4,2.5 2.419,2.504 2.435,2.515 2.446,2.531 2.45,2.55 2.45,2.55 2.45,2.7 2.446,2.719 2.435,2.735 2.419,2.746 2.4,2.75 2.4,2.75 2.05,2.75 2.012,2.758 1.979,2.779 1.958,2.812 1.95,2.85 1.95,2.85 1.95,3.15 1.946,3.169 1.935,3.185 1.919,3.196 1.9,3.2 1.9,3.2 1.75,3.2 1.725,3.193 1.707,3.175 1.7,3.15 1.7,3.15 1.7,2.55 1.704,2.531 1.715,2.515 1.731,2.504 1.75,2.5 1.75,2.5
  silkscreen extent -3.18,-3.37 2.6,3.3, body extent -2.25,-3 2.25,3, height 0.85
WEEE_Minimum [mil] "WEEElie bin"
  silkscreen extent -95,-172 99,104

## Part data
C1 C2 C3 C4: library part CMP-0008374-2, "CAP, CERM, 0.47 uF, 100 V, +/- 10%, X7R, 0805", Cap_Case=0805, Manufacturer=MuRata, Supplier Part Number 1=490-3326-1-ND, TempCo=X7R, Tolerance_%=10%, Value1=Unknown, Value2=100V, ValueDisplayed=0.47uF
C8: library part CMP-0011203-2, "CAP, AL, 33 uF, 100 V, +/- 20%, 0.7 ohm, AEC-Q200 Grade 2, SMD", Cap_Case=G, Manufacturer=Panasonic, Supplier Part Number 1=PCE3846CT-ND, Tolerance_%=20%, Value1="0.7 ohm", Value2=100V, ValueDisplayed=33uF
C9 C10 C11 C12 C13: library part CMP-0087970-1, "10µF ±10% 100V Ceramic Capacitor X7S 1210 (3225 Metric)", Manufacturer=Murata, TempCo=22%, Tolerance_%=10%, ValueDisplayed=10uF
C14: library part CMP-0080063-1, "CAP, CERM, 0.01 µF, 100 V,+/- 10%, X8R, AEC-Q200 Grade 0, 0603", Cap_Case=0603, Manufacturer=TDK, Supplier Part Number 1=445-8825-1-ND, TempCo=X8R, Tolerance_%=10%, Value2=100V, ValueDisplayed=0.01µF
C23: library part CMP-0086250-1, "CAP, CERM, 2.2 µF, 10 V,+/- 10%, X7S, AEC-Q200 Grade 1, 0402", Cap_Case=0402, Manufacturer=MuRata, TempCo=X7S, Tolerance_%=10%, Value2=10V, ValueDisplayed=2.2µF
C25 C32: library part CMP-0080610-1, "CAP, CERM, 0.1 µF, 25 V,+/- 10%, X7R, AEC-Q200 Grade 1, 0402", Cap_Case=0402, Manufacturer=TDK, Supplier Part Number 1=445-6902-1-ND, TempCo=X7R, Tolerance_%=10%, Value2=25V, ValueDisplayed=0.1µF
C26 C27 C28 C29: library part CMP-0096011-1, "Ceramic Capacitor for Automotive 47uF ±10% 10VDC X7S 1210 Embossed T/R"
C26 C27 C28 C29: library part CMP-0036912-1, "Cap Ceramic 22uF 25V X7R 20% Pad SMD 1210 +125°C Automotive T/R", Manufacturer=TDK, Operating Temperature Range="-55°C to +125°C", TempCo=15%, Temperature Characteristic=X7R, Tolerance_%=0.2%, ValueDisplayed=22uF
C30 C31: library part CMP-0006861-4, "CAP, CERM, 0.1 uF, 50 V, +/- 10%, X7R, 0603", Cap_Case=0603, Manufacturer=Kemet, Supplier Part Number 1=399-5089-1-ND, TempCo=X7R, Tolerance_%=10%, Value1=Unknown, Value2=50V, ValueDisplayed=0.1uF
C33: library part CMP-0078224-1, "CAP, CERM, 0.01 µF, 50 V,+/- 10%, X8R, AEC-Q200 Grade 0, 0402", Cap_Case=0402, Manufacturer=TDK, Supplier Part Number 1=445-12303-1-ND, TempCo=X8R, Tolerance_%=10%, Value2=50V, ValueDisplayed=0.01µF
C34: library part CMP-0006308-2, "CAP, CERM, 100 pF, 50 V, +/- 5%, C0G/NP0, AEC-Q200 Grade 1, 0402", Cap_Case=0402, Manufacturer=TDK, Supplier Part Number 1=445-5596-1-ND, TempCo=C0G/NP0, Tolerance_%=5%, Value1=Unknown, Value2=50V, ValueDisplayed=100pF
C35: library part CMP-0860832-1, "CAP, CERM, 47 pF, 50 V,+/- 5%, C0G/NP0, AEC-Q200 Grade 1, 0402", Cap_Case=0402, Manufacturer=TDK, TempCo=C0G/NP0, Tolerance_%=5%, Value2=50V, ValueDisplayed=47pF
C36: library part CMP-0006686-2, "CAP, CERM, 2700 pF, 50 V, +/- 10%, X7R, 0402", Cap_Case=0402, Manufacturer=MuRata, Supplier Part Number 1=490-1306-1-ND, TempCo=X7R, Tolerance_%=10%, Value1=Unknown, Value2=50V, ValueDisplayed=2700pF
C37: library part CMP-0124193-1, "100 µF 16 V Aluminum - Polymer Capacitors 2917 (7343 Metric) 12mOhm 2000 Hrs @ 105°C", Digikey Part Number=490-ECASD61C107M012KA0CT-ND, Leakage Current=480uA, Manufacturer=Murata, Mouser Part Number=81-ECASD61C107M012KA, Operating Temperature Range="-40°C to +105°C", Tolerance_%=20%, ValueDisplayed=100uF
"CAUTION HOT SURFACE": library part CMP-0074837-2, "IEC 61010-1 Hot Surface Warning", Manufacturer="Texas Instruments"
FID1 FID2 FID3 FID4 FID5 FID6: library part CMP-0077181-1, "Fiducial mark.  There is nothing to buy or mount.", Manufacturer=N/A
H1 H2 H3 H4: library part CMP-0003617-1, "Machine Screw, Round, #4-40 x 1/4, Nylon, Philips panhead", Manufacturer="B&F Fastener Supply", Supplier Part Number 1=H542-ND
H5 H6 H7 H8: library part CMP-0003610-1, "Standoff, Hex, 0.5\"L #4-40 Nylon", Manufacturer=Keystone, Supplier Part Number 1=36-1902C-ND
J1: library part CMP-0054978-1, "Therminal Block, 5 mm, 2-pole, Tin, TH", Manufacturer="TE Connectivity", Supplier Part Number 1=A98355-ND
J2 J3: library part CMP-0087729-1, "WP-THRSH 8 Pin PCB Screw Terminal, 85A, Solder, M5, Vertical", Current_A=85A, Manufacturer="Wurth Electronics"
J4: library part CMP-0075424-1, "Header, 100mil, 12x1, Gold, TH", Color=Black, Current_A=6.3A, Manufacturer=Samtec, Supplier Part Number 1=SAM1029-12-ND, Voltage_V=550V
L1: library part CMP-0093175-1, "Shielded Power Inductors 3.3uH 20% tol, 6.5mOhm 16.6A", Manufacturer=Coilcraft, Operating Temperature Range=to, Self Resonant Frequency=24MHz, Test Frequency=1MHz, Tolerance_%=20%
L2: library part CMP-0123970-1, "Power Choke Coil 4.7uH 20% 100kHz 4.7mOhm 27A AECQ200 13.3x12.8x8.0mm SMT", Manufacturer=Cyntec, Operating Temperature Range="-55°C to +180°C", Test Frequency=100kHz, Tolerance_%=20%
Logo1: library part CMP-0074844-1, Manufacturer="Texas Instruments"
Logo2: library part CMP-0074838-1, "Texas Instrument Corporate Signature"
Logo3: library part CMP-0074847-1, "FCC_disclaimer"
Logo4: library part CMP-0074769-1, Manufacturer="Texas Instruments"
R1: library part CMP-0020616-3, "RES, 0, 5%, 0.125 W, AEC-Q200 Grade 0, 0805", Manufacturer=Panasonic, Power_W=125mW, Supplier Part Number 1=P0.0ACT-ND, TempCo="600 ppm/C", Tolerance_%=5%, Value2=0.125W, Value_Code=0000, ValueDisplayed=0
R7 R29: library part CMP-0080661-1, "RES, 100 k, 1%, 0.0625 W, AEC-Q200 Grade 0, 0402", Manufacturer="Yageo America", Power_W=62.5mW, Supplier Part Number 1=YAG3434CT-ND, TempCo="100 ppm/C", Tolerance_%=1%, Value2=0.0625W, Value_Code=100k
R8: library part CMP-0022901-4, "RES, 200 k, 1%, 0.1 W, 0603", Manufacturer=Yageo, Power_W=100mW, Supplier Part Number 1=311-200KHRCT-ND, TempCo="100 ppm/C", Tolerance_%=1%, Value2=0.1W, Value_Code=200k
R9 R12: library part CMP-0078779-1, "RES, 10.0 k, 1%, 0.2 W, AEC-Q200 Grade 0, 0402", Manufacturer=Panasonic, Power_W=200mW, Supplier Part Number 1=P17230CT-ND, TempCo="100 ppm/C", Tolerance_%=1%, Value2=0.2W, Value_Code=10k0, ValueDisplayed=10.0k
R10: library part CMP-0026129-2, "RES, 1.00, 1%, 0.063 W, AEC-Q200 Grade 0, 0402", Manufacturer=Vishay-Dale, Power_W=63mW, Supplier Part Number 1=541-1.00LLCT-ND, TempCo="100 ppm/C", Tolerance_%=1%, Value2=0.063W, Value_Code=1R00, ValueDisplayed=1.00
R11: library part CMP-0124890-1, "1 mOhms ±5% 1.5W Chip Resistor Wide 1206 (3216 Metric), 0612 Automotive AEC-Q200, Current Sense Metal Foil", Digikey Part Number=408-KRL3216E-C-R001-J-T5CT-ND, Manufacturer=Susumu, Mouser Part Number=754-KRL3216ECR001JT5, Operating Temperature Range="-55°C to +175°C", Power_W=1.5W, TempCo=150ppm/°C, Tolerance_%=5%
R13 R16 R26: library part CMP-0026449-2, "RES, 54.9 k, 1%, 0.063 W, AEC-Q200 Grade 0, 0402", Manufacturer=Vishay-Dale, Power_W=63mW, Supplier Part Number 1=541-54.9KLCT-ND, TempCo="100 ppm/C", Tolerance_%=1%, Value2=0.063W, Value_Code=54k9, ValueDisplayed=54.9k
R14 R25 R27: library part CMP-0027007-2, "RES, 0, 5%, 0.063 W, AEC-Q200 Grade 0, 0402", Manufacturer="KOA Speer", Power_W=63mW, Supplier Part Number 1=660-RK73Z1ETTP, TempCo=ppm/C, Tolerance_%=5%, Value2=0.063W, Value_Code=0000, ValueDisplayed=0
R15 R17: library part CMP-0026703-1, "RES, 49.9, 1%, 0.1 W, AEC-Q200 Grade 0, 0402", Manufacturer=Panasonic, Power_W=100mW, Supplier Part Number 1=P49.9LCT-ND, TempCo="100 ppm/C", Tolerance_%=1%, Value2=0.1W, Value_Code=49R9, ValueDisplayed=49.9
R19: library part CMP-0025975-3, "RES, 11.0 k, 1%, 0.063 W, AEC-Q200 Grade 0, 0402", Manufacturer=Vishay-Dale, Power_W=63mW, Supplier Part Number 1=541-11.0KLCT-ND, TempCo="100 ppm/C", Tolerance_%=1%, Value2=0.063W, Value_Code=11k0, ValueDisplayed=11.0k
R20: library part CMP-0026591-2, "RES, 8.66 k, 1%, 0.063 W, AEC-Q200 Grade 0, 0402", Manufacturer=Vishay-Dale, Power_W=63mW, Supplier Part Number 1=541-8.66KLCT-ND, TempCo="100 ppm/C", Tolerance_%=1%, Value2=0.063W, Value_Code=8k66, ValueDisplayed=8.66k
R21 R24: library part CMP-0026605-2, "RES, 90.9 k, 1%, 0.063 W, AEC-Q200 Grade 0, 0402", Manufacturer=Vishay-Dale, Power_W=63mW, Supplier Part Number 1=541-90.9KLCT-ND, TempCo="100 ppm/C", Tolerance_%=1%, Value2=0.063W, Value_Code=90k9, ValueDisplayed=90.9k
R22: library part CMP-0026187-2, "RES, 23.7 k, 1%, 0.063 W, AEC-Q200 Grade 0, 0402", Manufacturer=Vishay-Dale, Power_W=63mW, Supplier Part Number 1=541-23.7KLCT-ND, TempCo="100 ppm/C", Tolerance_%=1%, Value2=0.063W, Value_Code=23k7, ValueDisplayed=23.7k
R28: library part CMP-0026783-1, "RES, 4.99 k, 0.1%, 0.063 W, 0402", Manufacturer=Panasonic, Power_W=63mW, Supplier Part Number 1=P4.99KDCCT-ND, TempCo="25 ppm/C", Tolerance_%=0.1%, Value2=0.063W, Value_Code=4k99, ValueDisplayed=4.99k
SH-J1 SH-J2: library part CMP-0078738-1, "Single Operation 2.54mm Pitch Open Top Jumper Socket", Manufacturer=Harwin, Supplier Part Number 1=952-2881-ND
TP1 TP2 TP3 TP4: library part CMP-0055162-1, "Test Point, Miniature, SMT", Manufacturer=Keystone, Supplier Part Number 1=36-5019TR-ND
U1: library part CMP-0125338-2, "LMG708B0", Manufacturer="Texas Instruments", Operating Temperature Range=to
ZZ1: library part CMP-0003616-3
ZZ2: library part CMP-0077236-1
ZZ3: library part CMP-0077237-1
ZZ4: library part CMP-0077238-1
ZZ5 ZZ6: library part CMP-0077238-1, "These assemblies must comply with workmanship standards IPC-A-610 Class 2, unless otherwise specified."

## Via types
v1: diameter 22, hole 10, Top Layer to Bottom Layer, tented both sides, 277 vias
v2: diameter 19.68, hole 7.87, Top Layer to Bottom Layer, tented both sides, 18 vias

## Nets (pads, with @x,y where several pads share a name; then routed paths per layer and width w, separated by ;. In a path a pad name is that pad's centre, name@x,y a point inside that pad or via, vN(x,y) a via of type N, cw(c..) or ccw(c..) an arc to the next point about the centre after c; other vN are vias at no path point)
AGND: C35.2 C36.2 R9.1 R16.1 R20.1 R21.1 R22.1 R24.1 R27.1 R28.1 U1.1 U1.16 | length 90.6
  Top Layer w10: 1541.77,835.62 1593.73,835.62 1611.79,853.68 U1.16@1611.79,866.8
BIAS: C32.1 R10.1 U1.3 | length 738.5
  Top Layer w9.8: U1.3@1743.22,915.43 1794.92,915.43 1811.51,898.84 v1(1817.45,898.84)
  Top Layer w10: v1(1817.45,898.84) 1819.32,898.84 1829.3,888.85 1843.03,888.85 C32.1@1846.88,885
  Signal Layer 2 w10: v1(1817.45,898.84) 1878.36,837.93 1977.15,837.93 v1(2272.43,542.65)
  Bottom Layer w10: 2272.43,522.97 v1(2272.43,542.65)
COMP: C35.1 R19.2 U1.21 | length 109.3
  Top Layer w9: R19.2@1709.02,800.6 1708.31,801.31 1708.96,801.31 1714,806.35 1714,827.32 ; R19.2@1714.61,798.59 1716.49,796.71 C35.1@1716.49,759
  Top Layer w10: U1.21@1710.21,866.8 1710.21,829.28 1711.4,828.09
EN: J4.2 R8.1 R9.2 U1.11 | length 851.2
  Top Layer w9: v1(1514.55,965.88) 1518.07,965.88 1529.56,954.39 U1.11@1578.32,954.39
  Top Layer w10: R8.1@1465.34,975.72 1472.69,968.38 R9.2@1472.69,937.2 ; R8.1@1465.34,977.69 1476.09,966.94 1487.49,966.94 1488.55,965.88 v1(1514.55,965.88)
  Signal Layer 2 w10: J4.2@1317.7,395.02 1425.97,503.28 1425.97,936.35 1455.5,965.88 v1(1514.55,965.88)
FB: R25.1 R26.1 R28.2 U1.20 | length 368.8
  Top Layer w10: R28.2@1676.94,771.66 1681.67,776.4 1681.67,810.55 v1(1683.46,812.34) ; v1@1681.87,814 1689.85,821.98 U1.20@1689.85,867.24 ; v1(1849.2,729.66) R25.1@1849.2,759.19 R26.1@1888.57,759.19
  Signal Layer 4 w9.8: v1(1683.46,812.34) 1766.14,729.66 v1(1849.2,729.66)
FPWM/SYNC: J4.5 U1.13 | length 668.6
  Top Layer w9.8: v1(1534.67,912.11) 1538.01,915.45 U1.13@1577.84,915.45
  Signal Layer 2 w9.8: v1(1534.67,912.11) 1534.35,912.42 1486.52,912.42 1480.78,906.68 1480.78,872.22 1544.08,808.92 1544.08,466.92 J4.5@1615.98,395.02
